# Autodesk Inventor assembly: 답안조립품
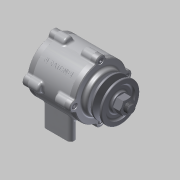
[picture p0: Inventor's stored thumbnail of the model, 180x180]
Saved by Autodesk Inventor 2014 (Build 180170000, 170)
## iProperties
Created: 2015-03
Part Number: 답안조립품
Document SubType Name: Assembly
Designer: MYHOME
Author: MYHOME
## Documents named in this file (11)
- C:\Documents and Settings\MYHOME\바탕 화면\450306V1022\답안조립품.iam
- C:\Documents and Settings\MYHOME\바탕 화면\450306V1022\본체.ipt
- C:\Documents and Settings\MYHOME\바탕 화면\450306V1022\커버.ipt
- C:\Documents and Settings\MYHOME\바탕 화면\450306V1022\M 4 x 12.ipt
- C:\Documents and Settings\MYHOME\바탕 화면\450306V1022\오일실.ipt
- C:\Documents and Settings\MYHOME\바탕 화면\450306V1022\커버2.ipt
- C:\Documents and Settings\MYHOME\바탕 화면\450306V1022\축.ipt
- C:\Documents and Settings\MYHOME\바탕 화면\450306V1022\키(4 x 4 x 12).ipt
- C:\Documents and Settings\MYHOME\바탕 화면\450306V1022\베어링 6204.ipt
- C:\Documents and Settings\MYHOME\바탕 화면\450306V1022\V벨트풀리.ipt
- C:\Documents and Settings\MYHOME\바탕 화면\450306V1022\너트 M12x1.25.ipt
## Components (14 placed, 6 different names)
1. KS B 2804 D D - 20 32 8:1
2. KS B 1311 (I) 4 x 4 x 12:1
3. KS B 2023 6204 - 20 x 47 x 14:1
4. KS B 2023 6204 - 20 x 47 x 14:2
5. 그루브 풀리1:1
6. KS B 1012 클래스 1 일반 - 미터 M12x1.25:1
7. KS B 1003 - 미터 M 4 x 12:1
8. KS B 1003 - 미터 M 4 x 12:2
9. KS B 1003 - 미터 M 4 x 12:3
10. KS B 1003 - 미터 M 4 x 12:4
11. KS B 1003 - 미터 M 4 x 12:5
12. KS B 1003 - 미터 M 4 x 12:6
13. KS B 1003 - 미터 M 4 x 12:7
14. KS B 1003 - 미터 M 4 x 12:8
